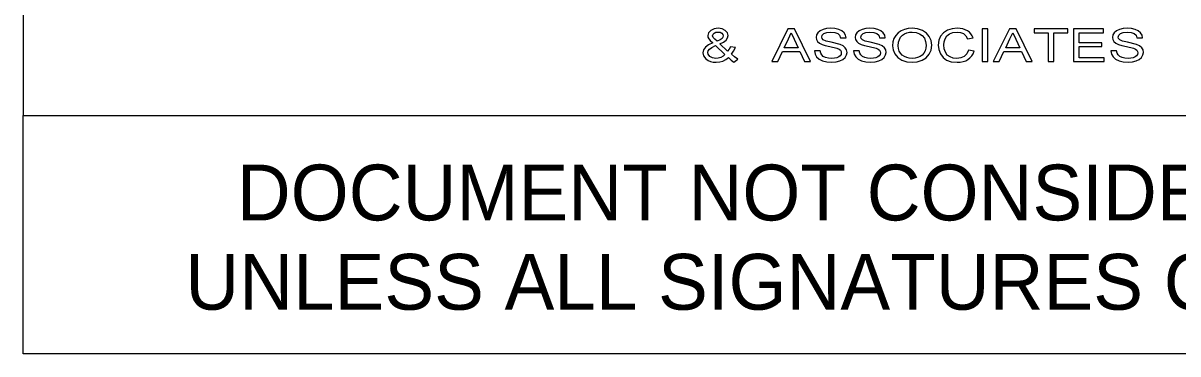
# Model space of a CAD drawing. Extents: x 406996 to 407670, y -135414 to -134930.
# Drawn here: x 407582.98 to 407628.52, y -134973.58 to -134960.54 of the extents above; entities that cross this region are included whole.
import ezdxf

# ---------------------------------------------------------------- set-up
doc = ezdxf.new("R2010")
doc.units = 0
for name, color, linetype in [('Default', 7, 'Continuous'), ('Sheet Sticker Exception Certification CELL', 7, 'Continuous'), ('Sheet Typical CELL', 7, 'Continuous')]:
    doc.layers.add(name, color=color, linetype=linetype)

msp = doc.modelspace()

# ---------------------------------------------------------------- linework, layer by layer
at = {"layer": 'Default'}
for points in [[(407610.797, -134961.903), (407610.904, -134962.008), (407611.008, -134962.084), (407611.168, -134961.961), (407611.032, -134961.873), (407610.912, -134961.767), (407611.002, -134961.653), (407611.072, -134961.505), (407610.879, -134961.47), (407610.827, -134961.566), (407610.758, -134961.648), (407610.457, -134961.358), (407610.599, -134961.287), (407610.701, -134961.209), (407610.762, -134961.124), (407610.783, -134961.031), (407610.755, -134960.921), (407610.674, -134960.828), (407610.549, -134960.765), (407610.394, -134960.744), (407610.231, -134960.766), (407610.098, -134960.831), (407610.009, -134960.926), (407609.98, -134961.036), (407609.99, -134961.097), (407610.02, -134961.159), (407610.082, -134961.233), (407610.184, -134961.325), (407610.01, -134961.403), (407609.886, -134961.493), (407609.812, -134961.595), (407609.787, -134961.709), (407609.817, -134961.837), (407609.909, -134961.951), (407609.991, -134962.01), (407610.086, -134962.052), (407610.195, -134962.076), (407610.316, -134962.084), (407610.451, -134962.073), (407610.576, -134962.039), (407610.691, -134961.982), (407610.797, -134961.903)], [(407610.352, -134961.257), (407610.256, -134961.174), (407610.193, -134961.102), (407610.172, -134961.038), (407610.188, -134960.982), (407610.233, -134960.935), (407610.3, -134960.904), (407610.384, -134960.893), (407610.465, -134960.904), (407610.531, -134960.935), (407610.575, -134960.984), (407610.59, -134961.045), (407610.579, -134961.1), (407610.546, -134961.148), (407610.475, -134961.199), (407610.352, -134961.257)], [(407612.506, -134962.06), (407612.742, -134962.06), (407612.927, -134961.663), (407613.617, -134961.663), (407613.802, -134962.06), (407614.039, -134962.06), (407613.405, -134960.769), (407613.139, -134960.769), (407612.506, -134962.06)], [(407617.272, -134961.431), (407617.295, -134961.598), (407617.365, -134961.755), (407617.478, -134961.892), (407617.636, -134961.996), (407617.827, -134962.062), (407618.043, -134962.084), (407618.246, -134962.065), (407618.434, -134962.005), (407618.595, -134961.906), (407618.715, -134961.769), (407618.788, -134961.604), (407618.814, -134961.417), (407618.79, -134961.232), (407618.719, -134961.069), (407618.604, -134960.932), (407618.446, -134960.83), (407618.256, -134960.766), (407618.044, -134960.744), (407617.881, -134960.755), (407617.734, -134960.79), (407617.603, -134960.847), (407617.487, -134960.927), (407617.393, -134961.027), (407617.326, -134961.144), (407617.285, -134961.279), (407617.272, -134961.431)], [(407617.497, -134961.434), (407617.507, -134961.298), (407617.537, -134961.184), (407617.587, -134961.09), (407617.659, -134961.017), (407617.743, -134960.963), (407617.836, -134960.924), (407617.936, -134960.901), (407618.045, -134960.893), (407618.195, -134960.909), (407618.33, -134960.958), (407618.441, -134961.036), (407618.523, -134961.14), (407618.572, -134961.268), (407618.589, -134961.415), (407618.579, -134961.533), (407618.55, -134961.636), (407618.502, -134961.725), (407618.434, -134961.8), (407618.352, -134961.86), (407618.259, -134961.902), (407618.155, -134961.927), (407618.042, -134961.936), (407617.93, -134961.927), (407617.827, -134961.902), (407617.734, -134961.86), (407617.652, -134961.801), (407617.584, -134961.728), (407617.536, -134961.642), (407617.507, -134961.545), (407617.497, -134961.434)], [(407621.242, -134962.06), (407621.479, -134962.06), (407621.664, -134961.663), (407622.354, -134961.663), (407622.539, -134962.06), (407622.776, -134962.06), (407622.142, -134960.769), (407621.876, -134960.769), (407621.242, -134962.06)], [(407612.995, -134961.514), (407613.161, -134961.156), (407613.272, -134960.918), (407613.392, -134961.176), (407613.549, -134961.514), (407612.995, -134961.514)], [(407621.732, -134961.514), (407621.898, -134961.156), (407622.009, -134960.918), (407622.129, -134961.176), (407622.286, -134961.514), (407621.732, -134961.514)], [(407610.661, -134961.785), (407610.589, -134961.846), (407610.498, -134961.894), (407610.397, -134961.925), (407610.3, -134961.936), (407610.164, -134961.915), (407610.063, -134961.853), (407610, -134961.772), (407609.98, -134961.694), (407609.995, -134961.631), (407610.044, -134961.567), (407610.137, -134961.5), (407610.29, -134961.427), (407610.661, -134961.785)]]:
    msp.add_lwpolyline(points, dxfattribs=at)
for points in [[(407614.188, -134961.638), (407614.212, -134961.763), (407614.276, -134961.875), (407614.376, -134961.967), (407614.509, -134962.033), (407614.674, -134962.072), (407614.876, -134962.084), (407615.04, -134962.072), (407615.187, -134962.034), (407615.309, -134961.973), (407615.399, -134961.892), (407615.454, -134961.798), (407615.473, -134961.697), (407615.456, -134961.599), (407615.405, -134961.513), (407615.32, -134961.44), (407615.198, -134961.38), (407614.849, -134961.297), (407614.645, -134961.25), (407614.538, -134961.204), (407614.492, -134961.153), (407614.477, -134961.089), (407614.498, -134961.014), (407614.562, -134960.95), (407614.673, -134960.907), (407614.836, -134960.893), (407614.993, -134960.907), (407615.107, -134960.949), (407615.181, -134961.02), (407615.216, -134961.116), (407615.441, -134961.116), (407615.417, -134961.013), (407615.36, -134960.92), (407615.269, -134960.844), (407615.147, -134960.788), (407614.997, -134960.755), (407614.827, -134960.744), (407614.669, -134960.755), (407614.527, -134960.788), (407614.409, -134960.843), (407614.322, -134960.918), (407614.27, -134961.007), (407614.252, -134961.102), (407614.267, -134961.187), (407614.311, -134961.264), (407614.386, -134961.33), (407614.492, -134961.385), (407614.616, -134961.424), (407614.8, -134961.466), (407615.078, -134961.529), (407615.161, -134961.565), (407615.212, -134961.607), (407615.239, -134961.657), (407615.248, -134961.715), (407615.237, -134961.774), (407615.204, -134961.827), (407615.15, -134961.872), (407615.072, -134961.906), (407614.976, -134961.929), (407614.867, -134961.936), (407614.742, -134961.926), (407614.631, -134961.897), (407614.539, -134961.853), (407614.476, -134961.797), (407614.435, -134961.726), (407614.413, -134961.638)], [(407615.73, -134961.638), (407615.754, -134961.763), (407615.818, -134961.875), (407615.918, -134961.967), (407616.051, -134962.033), (407616.216, -134962.072), (407616.418, -134962.084), (407616.582, -134962.072), (407616.729, -134962.034), (407616.851, -134961.973), (407616.941, -134961.892), (407616.996, -134961.798), (407617.015, -134961.697), (407616.998, -134961.599), (407616.947, -134961.513), (407616.862, -134961.44), (407616.74, -134961.38), (407616.391, -134961.297), (407616.187, -134961.25), (407616.08, -134961.204), (407616.034, -134961.153), (407616.019, -134961.089), (407616.04, -134961.014), (407616.104, -134960.95), (407616.215, -134960.907), (407616.378, -134960.893), (407616.536, -134960.907), (407616.649, -134960.949), (407616.723, -134961.02), (407616.758, -134961.116), (407616.983, -134961.116), (407616.96, -134961.013), (407616.902, -134960.92), (407616.811, -134960.844), (407616.689, -134960.788), (407616.539, -134960.755), (407616.369, -134960.744), (407616.211, -134960.755), (407616.069, -134960.788), (407615.951, -134960.843), (407615.865, -134960.918), (407615.812, -134961.007), (407615.794, -134961.102), (407615.809, -134961.187), (407615.854, -134961.264), (407615.928, -134961.33), (407616.034, -134961.385), (407616.158, -134961.424), (407616.342, -134961.466), (407616.62, -134961.529), (407616.703, -134961.565), (407616.754, -134961.607), (407616.781, -134961.657), (407616.79, -134961.715), (407616.779, -134961.774), (407616.746, -134961.827), (407616.692, -134961.872), (407616.614, -134961.906), (407616.518, -134961.929), (407616.409, -134961.936), (407616.284, -134961.926), (407616.173, -134961.897), (407616.081, -134961.853), (407616.018, -134961.797), (407615.977, -134961.726), (407615.955, -134961.638)], [(407620.259, -134961.607), (407620.196, -134961.75), (407620.095, -134961.853), (407619.961, -134961.915), (407619.801, -134961.936), (407619.662, -134961.92), (407619.535, -134961.875), (407619.428, -134961.799), (407619.353, -134961.691), (407619.31, -134961.558), (407619.295, -134961.404), (407619.307, -134961.278), (407619.344, -134961.156), (407619.41, -134961.048), (407619.513, -134960.964), (407619.648, -134960.911), (407619.812, -134960.893), (407619.954, -134960.909), (407620.07, -134960.957), (407620.16, -134961.041), (407620.227, -134961.162), (407620.451, -134961.123), (407620.413, -134961.038), (407620.362, -134960.963), (407620.299, -134960.898), (407620.224, -134960.843), (407620.138, -134960.8), (407620.042, -134960.769), (407619.937, -134960.75), (407619.822, -134960.744), (407619.62, -134960.764), (407619.436, -134960.822), (407619.28, -134960.919), (407619.165, -134961.051), (407619.094, -134961.215), (407619.07, -134961.405), (407619.092, -134961.585), (407619.155, -134961.752), (407619.259, -134961.895), (407619.401, -134961.999), (407619.587, -134962.063), (407619.822, -134962.084), (407619.942, -134962.078), (407620.052, -134962.057), (407620.153, -134962.022), (407620.244, -134961.973), (407620.323, -134961.911), (407620.39, -134961.837), (407620.443, -134961.75), (407620.484, -134961.65)], [(407620.804, -134962.06), (407621.029, -134962.06), (407621.029, -134960.769), (407620.804, -134960.769)], [(407623.406, -134962.06), (407623.631, -134962.06), (407623.631, -134960.918), (407624.177, -134960.918), (407624.177, -134960.769), (407622.86, -134960.769), (407622.86, -134960.918), (407623.406, -134960.918)], [(407624.401, -134962.06), (407625.621, -134962.06), (407625.621, -134961.911), (407624.626, -134961.911), (407624.626, -134961.464), (407625.525, -134961.464), (407625.525, -134961.315), (407624.626, -134961.315), (407624.626, -134960.918), (407625.589, -134960.918), (407625.589, -134960.769), (407624.401, -134960.769)], [(407625.879, -134961.638), (407625.903, -134961.763), (407625.967, -134961.875), (407626.067, -134961.967), (407626.2, -134962.033), (407626.365, -134962.072), (407626.567, -134962.084), (407626.731, -134962.072), (407626.878, -134962.034), (407627, -134961.973), (407627.09, -134961.892), (407627.145, -134961.797), (407627.164, -134961.697), (407627.147, -134961.599), (407627.096, -134961.513), (407627.011, -134961.44), (407626.889, -134961.38), (407626.54, -134961.297), (407626.336, -134961.25), (407626.229, -134961.204), (407626.183, -134961.153), (407626.168, -134961.089), (407626.189, -134961.014), (407626.253, -134960.95), (407626.364, -134960.907), (407626.527, -134960.893), (407626.684, -134960.907), (407626.798, -134960.949), (407626.871, -134961.02), (407626.907, -134961.116), (407627.131, -134961.116), (407627.108, -134961.013), (407627.051, -134960.92), (407626.96, -134960.844), (407626.838, -134960.788), (407626.688, -134960.755), (407626.518, -134960.744), (407626.36, -134960.755), (407626.218, -134960.788), (407626.1, -134960.843), (407626.013, -134960.918), (407625.961, -134961.007), (407625.943, -134961.102), (407625.958, -134961.187), (407626.002, -134961.264), (407626.077, -134961.33), (407626.183, -134961.385), (407626.307, -134961.424), (407626.491, -134961.466), (407626.769, -134961.529), (407626.851, -134961.565), (407626.903, -134961.607), (407626.93, -134961.657), (407626.939, -134961.715), (407626.928, -134961.774), (407626.895, -134961.827), (407626.84, -134961.872), (407626.763, -134961.906), (407626.667, -134961.929), (407626.557, -134961.936), (407626.432, -134961.926), (407626.322, -134961.897), (407626.23, -134961.853), (407626.167, -134961.797), (407626.126, -134961.726), (407626.104, -134961.638)]]:
    msp.add_lwpolyline(points, close=True, dxfattribs=at)
at = {"layer": 'Sheet Sticker Exception Certification CELL'}
for p, q in [((407582.98, -134973.582), (407582.98, -134964.182)), ((407582.98, -134964.182), (407662.995, -134964.182)), ((407662.995, -134973.582), (407582.98, -134973.582))]:
    msp.add_line(p, q, dxfattribs=at)
at = {"layer": 'Sheet Typical CELL'}
msp.add_lwpolyline([(407662.995, -134950.111), (407582.98, -134950.111), (407582.98, -134964.182), (407662.995, -134964.182)], close=True, dxfattribs=at)

# ---------------------------------------------------------------- texts
at = {"layer": 'Sheet Sticker Exception Certification CELL'}
for s, p in [('DOCUMENT NOT CONSIDERED FINAL', (407591.408, -134968.32)), ('UNLESS ALL SIGNATURES COMPLETED', (407589.38, -134971.84))]:
    msp.add_text(s, height=2.2, dxfattribs=at).set_placement(p)

doc.saveas('drawing.dxf')
